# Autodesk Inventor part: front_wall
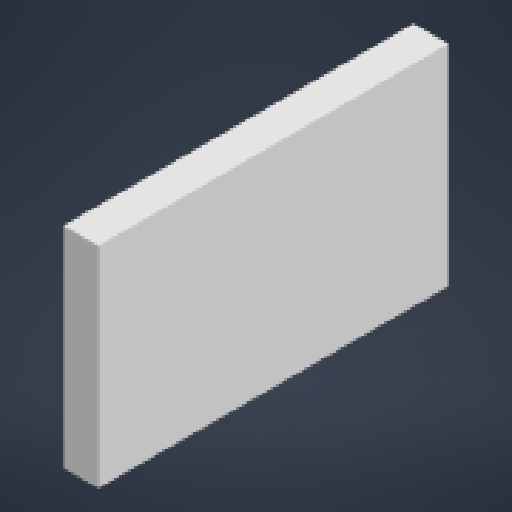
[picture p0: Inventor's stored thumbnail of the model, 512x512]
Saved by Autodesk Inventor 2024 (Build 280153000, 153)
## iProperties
Created: 2023-09
Part Number: front_wall
Material: Generic
Document SubType Name: Modeling
Designer: mammothbane
Density: 1 g/cm^3
Appearance: Default
Author: mammothbane
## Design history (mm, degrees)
sketch "Sketch1"
  geometry: L1 (50, 300)-(-50, 300); L2 (-50, 300)-(-50, -300); L3 (-50, -300)-(50, -300); L4 (50, -300)-(50, 300); L5 (50, 300)-(-50, -300); L6 (-50, 300)-(50, -300); 1 further point
  constraints: 12 end point, 2 midpoint, 2 parallel, 1 horizontal, 1 perpendicular
  dimensions: "width" = 100 distance of L3.end L2.end; "length" = 600 distance of L2.end L1.end
extrude "Extrusion1" new body sketch "Sketch1" taper "d3" = 0 deg; distance "height" = 1000
body "Solid1"
